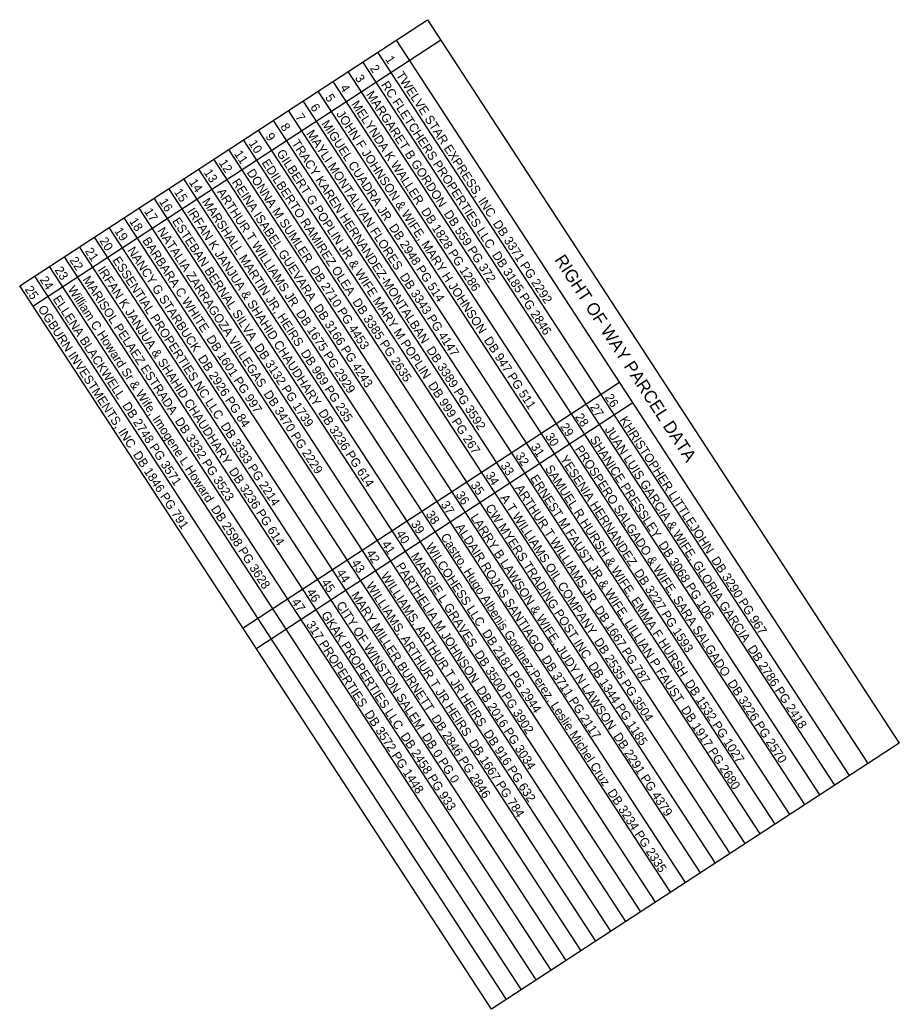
# Model space of a CAD drawing. Extents: x 1638966 to 1642158, y 841755 to 844938.
# Drawn here: x 1641185 to 1641630, y 844437 to 844938 of the extents above; entities that cross this region are included whole.
import ezdxf

# ---------------------------------------------------------------- set-up
doc = ezdxf.new("R2010")
doc.units = 0
doc.layers.add('Exist Guardrail', color=7, linetype='Continuous')

msp = doc.modelspace()

# ---------------------------------------------------------------- linework, layer by layer
at = {"layer": 'Exist Guardrail'}
for p, q in [((1641397.77, 844927.46), (1641191.19, 844792.67)), ((1641375.13, 844927.43), (1641614.09, 844561.22)), ((1641604.91, 844555.22), (1641365.94, 844921.44)), ((1641597.35, 844550.29), (1641358.38, 844916.51)), ((1641589.79, 844545.36), (1641350.83, 844911.57)), ((1641582.23, 844540.43), (1641343.27, 844906.64)), ((1641574.68, 844535.5), (1641335.71, 844901.71)), ((1641567.12, 844530.57), (1641328.15, 844896.78)), ((1641559.56, 844525.63), (1641320.59, 844891.85)), ((1641552, 844520.7), (1641313.03, 844886.91)), ((1641544.44, 844515.77), (1641305.48, 844881.98)), ((1641536.89, 844510.84), (1641297.92, 844877.05)), ((1641529.33, 844505.91), (1641290.36, 844872.12)), ((1641521.77, 844500.97), (1641282.8, 844867.19)), ((1641514.21, 844496.04), (1641275.24, 844862.25)), ((1641506.65, 844491.11), (1641267.69, 844857.32)), ((1641499.09, 844486.18), (1641260.13, 844852.39)), ((1641491.54, 844481.25), (1641252.57, 844847.46)), ((1641483.98, 844476.31), (1641245.01, 844842.53)), ((1641476.42, 844471.38), (1641237.45, 844837.59)), ((1641468.86, 844466.45), (1641229.89, 844832.66)), ((1641461.3, 844461.52), (1641222.34, 844827.73)), ((1641453.75, 844456.59), (1641214.78, 844822.8)), ((1641438.63, 844446.72), (1641199.66, 844812.93)), ((1641446.19, 844451.65), (1641207.22, 844817.87)), ((1641431.07, 844441.79), (1641192.1, 844808)), ((1641488.27, 844754.18), (1641297.75, 844629.86)), ((1641495.15, 844743.83), (1641304.64, 844619.52))]:
    msp.add_line(p, q, dxfattribs=at)
msp.add_lwpolyline([(1641391.07, 844937.83), (1641630.03, 844571.62), (1641423.51, 844436.86), (1641184.55, 844803.07)], close=True, dxfattribs=at)

# ---------------------------------------------------------------- texts
for s, height, p in [('1', 4.51, (1641369.51, 844917.84)), ('2', 4.51, (1641361.72, 844913.26)), ('3', 4.51, (1641354.15, 844908.34)), ('TWELVE STAR EXPRESS, INC  DB 3371 PG 2292', 4.5125, (1641374.92, 844909.86)), ('4', 4.51, (1641346.6, 844903.4)), ('RC FLETCHERS PROPERTIES LLC  DB 3185 PG 2846', 4.5125, (1641367.36, 844904.93)), ('5', 4.51, (1641339.03, 844898.49)), ('MARGARET B GORDON  DB 559 PG 372', 4.5125, (1641359.8, 844900)), ('6', 4.51, (1641331.48, 844893.55)), ('MELYNDA K WALLER  DB 1828 PG 1286', 4.5125, (1641352.24, 844895.07)), ('7', 4.51, (1641323.92, 844888.62)), ('JOHN F JOHNSON & WIFE, MARY H JOHNSON  DB 947 PG 511', 4.5125, (1641344.68, 844890.13)), ('8', 4.51, (1641316.36, 844883.69)), ('MIGUEL CUADRA JR  DB 2948 PG 514', 4.5125, (1641337.13, 844885.2)), ('9', 4.51, (1641308.8, 844878.75)), ('MAYLI MONTALVAN FLORES  DB 3343 PG 4147', 4.5125, (1641329.57, 844880.27)), ('10', 4.512, (1641300.29, 844875.28)), ('TRACY KAREN HERNANDEZ-MONTALBAN  DB 3389 PG 3592', 4.5125, (1641322.01, 844875.34)), ('11', 4.512, (1641292.97, 844869.99)), ('GILBERT G POPLIN JR & WIFE MARY M POPLIN  DB 999 PG 267', 4.5125, (1641314.45, 844870.41)), ('12', 4.512, (1641285.18, 844865.4)), ('EDILBERTO RAMIREZ OLEA  DB 3385 PG 2635', 4.5125, (1641306.89, 844865.47)), ('13', 4.512, (1641277.61, 844860.49)), ('DONNA M SUMLER  DB 2710 PG 4453', 4.5125, (1641299.33, 844860.54)), ('14', 4.512, (1641270.06, 844855.55)), ('REINA ISABEL GUEVARA  DB 3166 PG 4243', 4.5125, (1641291.78, 844855.61)), ('15', 4.512, (1641262.49, 844850.64)), ('ARTHUR T WILLIAMS JR  DB 1675 PG 2929', 4.5125, (1641284.22, 844850.68)), ('16', 4.512, (1641254.94, 844845.7)), ('MARSHALL MARTIN JR, HEIRS  DB 969 PG 235', 4.5125, (1641276.66, 844845.75)), ('17', 4.512, (1641247.38, 844840.76)), ('IRFAN K JANJUA & SHAHID CHAUDHARY  DB 3236 PG 614', 4.5125, (1641269.1, 844840.81)), ('18', 4.512, (1641239.82, 844835.83)), ('NATALIA ZARRAGOZA VILLEGAS  DB 3470 PG 2229', 4.5125, (1641253.99, 844830.95)), ('ESTEBAN BERNAL SILVA  DB 3132 PG 1739', 4.5125, (1641261.54, 844835.88)), ('19', 4.512, (1641232.26, 844830.9)), ('BARBARA C WHITE  DB 1601 PG 997', 4.5125, (1641246.43, 844826.02)), ('20', 4.512, (1641224.71, 844825.96)), ('NANCY G STARBUCK  DB 2926 PG 84', 4.5125, (1641238.87, 844821.09)), ('21', 4.512, (1641217.38, 844820.67)), ('ESSENTIAL PROPERTIES NC LLC  DB 3333 PG 2214', 4.5125, (1641231.31, 844816.15)), ('RIGHT OF WAY PARCEL DATA', 6.3175, (1641455.15, 844816.32)), ('23', 4.512, (1641202.03, 844811.17)), ('22', 4.512, (1641209.6, 844816.08)), ('IRFAN K JANJUA & SHAHID CHAUDHARY  DB 3236 PG 614', 4.5125, (1641223.75, 844811.22)), ('24', 4.512, (1641194.48, 844806.23)), ('MARISOL PELAEZ ESTRADA  DB 3332 PG 3523', 4.5125, (1641216.19, 844806.29)), ('25', 4.512, (1641186.9, 844801.32)), ('William C Howard Sr & Wife, Imogene L Howard  DB 2598 PG 3628', 4.5125, (1641208.64, 844801.36)), ('ELLENA BLACKWELL  DB 2748 PG 3571', 4.5125, (1641201.08, 844796.43)), ('OGBURN INVESTMENTS, INC  DB 1846 PG 791', 4.5125, (1641193.52, 844791.49)), ('26', 4.512, (1641480.76, 844746.67)), ('27', 4.512, (1641473.2, 844741.74)), ('28', 4.512, (1641465.64, 844736.81)), ('29', 4.512, (1641458.08, 844731.88)), ('KHRISTOPHER LITTLEJOHN  DB 3290 PG 967', 4.5125, (1641488.22, 844735.25)), ('30', 4.512, (1641450.53, 844726.93)), ('JUAN LUIS GARCIA & WIFE, GLORIA GARCIA  DB 2786 PG 2418', 4.5125, (1641480.67, 844730.32)), ('31', 4.512, (1641443.21, 844721.64)), ('SHANICE PRESSLEY  DB 3068 PG 106', 4.5125, (1641473.11, 844725.39)), ('32', 4.512, (1641435.42, 844717.06)), ('YESENIA HERNANDEZ  DB 3227 PG 1593', 4.5125, (1641457.99, 844715.52)), ('PROSPERO SALGADO & WIFE, SARA SALGADO  DB 3226 PG 2570', 4.5125, (1641465.55, 844720.46)), ('33', 4.512, (1641427.85, 844712.15)), ('34', 4.512, (1641420.3, 844707.2)), ('SAMUEL R HURSH & WIFE, EMMA F HURSH  DB 1532 PG 1027', 4.5125, (1641450.43, 844710.59)), ('35', 4.512, (1641412.73, 844702.3)), ('ERNEST M FAUST JR & WIFE, LILLIAN P FAUST  DB 1917 PG 2680', 4.5125, (1641442.88, 844705.66)), ('36', 4.512, (1641405.18, 844697.35)), ('ARTHUR T WILLIAMS JR  DB 1667 PG 787', 4.5125, (1641435.32, 844700.73)), ('37', 4.512, (1641397.62, 844692.42)), ('A T WILLIAMS OIL COMPANY  DB 2535 PG 3504', 4.5125, (1641427.76, 844695.8)), ('38', 4.512, (1641390.06, 844687.49)), ('LARRY B LAWSON & WIFE, JUDY N LAWSON  DB 2291 PG 4379', 4.5125, (1641412.64, 844685.93)), ('CW MYERS TRADING POST INC  DB 1344 PG 1185', 4.5125, (1641420.2, 844690.86)), ('39', 4.512, (1641382.5, 844682.56)), ('40', 4.512, (1641374.95, 844677.61)), ('ALDAIR ROJAS SANTIAGO  DB 3711 PG 2117', 4.5125, (1641405.08, 844681)), ('41', 4.512, (1641367.63, 844672.32)), ('WILCOHESS LLC  DB 2181 PG 2944', 4.5125, (1641389.97, 844671.14)), ('Castro, Hugo Albenis Godinez;Perez, Leslie Michel Cruz  DB 3234 PG 2335', 4.5125, (1641397.53, 844676.07)), ('42', 4.512, (1641359.84, 844667.74)), ('MARGIE L GRAVES  DB 3500 PG 3902', 4.5125, (1641382.41, 844666.2)), ('43', 4.512, (1641352.27, 844662.83)), ('PARTHELIA M JOHNSON  DB 2016 PG 3034', 4.5125, (1641374.85, 844661.27)), ('44', 4.512, (1641344.72, 844657.88)), ('WILLIAMS, ARTHUR T JR HEIRS  DB 916 PG 632', 4.5125, (1641367.29, 844656.34)), ('45', 4.512, (1641337.14, 844652.98)), ('WILLIAMS, ARTHUR T JR HEIRS  DB 1667 PG 784', 4.5125, (1641359.74, 844651.41)), ('46', 4.512, (1641329.6, 844648.03)), ('MARY MILLER BURNETT  DB 2846 PG 2846', 4.5125, (1641352.18, 844646.48)), ('47', 4.512, (1641322.04, 844643.1)), ('CITY OF WINSTON SALEM  DB 0 PG 0', 4.5125, (1641344.62, 844641.54)), ('GKAK PROPERTIES LLC  DB 2458 PG 933', 4.5125, (1641337.06, 844636.61)), ('317 PROPERTIES  DB 3572 PG 1448', 4.5125, (1641329.5, 844631.68))]:
    msp.add_text(s, height=height, rotation=303.1259, dxfattribs=at).set_placement(p)

doc.saveas('drawing.dxf')
